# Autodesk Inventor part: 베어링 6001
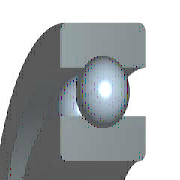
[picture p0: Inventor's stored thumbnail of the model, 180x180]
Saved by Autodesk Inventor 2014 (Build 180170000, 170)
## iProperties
Created: 2012-02
Part Number: 베어링 6001
Material: 강철, 연강
Description: 깊은 그루브 볼 베어링
Document SubType Name: Modeling
Standard: KS B 2023
Designer: mduedu
Standards Organization: KS
Language: ko-KR
Size Designation: 6001 - 12 x 28 x 8
Categories: <MemberInstance><Categories><Category DisplayName="샤프트 부품" InternalName="7f7aeb1f-a693-4053-b835-cee3144e0d98" Mnemonic="SHFT"><Category DisplayName="베어링" Inter
Density: 7.86 g/cm^3
Mass: 21.4855 g
Surface Area: 31.1809 cm^2
Volume: 2.73352 cm^3
Appearance: 노란색
IsCustomPart: 1
Author: mduedu
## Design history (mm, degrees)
sketch "스케치" dims "d0" = 4.16 (= -0.26 x WD + 0.26 x BD)
  geometry: L1 (1.92, 10)-(6.08, 10); L2 (4, 10)-(4, 7.92); L3 (4, 10)-(4, 12.08); L4 (2.454, 8.608)-(0, 8.608); L5 (0, 6)-(8, 6); L6 (2.454, 11.392)-(0, 11.392); L7 (0, 14)-(8, 14); L8 (8, 6)-(8, 8.608); L9 (5.546, 8.608)-(8, 8.608); L10 (5.546, 11.392)-(8, 11.392); L11 (8, 14)-(8, 11.392); L12 (-1.4, 0)-(8.4, 0) reference; L13 (0, -0.3)-(0, 5.3) reference
  constraints: 22 end point, 4 point on line, 2 collinear, 2 perpendicular, 2 symmetric about line, 1 midpoint, 1 parallel, 14 other
  dimensions: "d9" = 12 diameter of L5 L12 (= WD); "d11" = 28 diameter of L7 L12 (= BD); "d12" = 8 distance between parallel lines of L8 L13 (= KB); "d13" = 17.216 diameter of L9 L12 (= 0.326 x BD + 0.674 x WD)
revolve "본체" stored, may be unused: angle "d6" = 90 deg
revolve "볼" stored, may be unused: angle "d7" = 90 deg
pattern_circular "IDS_ARRAYBALL[SIMPL:T]" dims angle "d3" = 360 deg
body "Solid1"
fillet "모깎기1" dims "d1" = 0.3 (= KRS)
other parameters: "WD" = 12 [user parameter; used in 5 equation terms], "BD" = 28 [user parameter; used in 5 equation terms], "KB" = 8 [user parameter; used in 1 equation term], "KRS" = 0.3 [user parameter; used in 1 equation term], "d4" = 0, "d5" = 0, "d8" = 0, "d14" = 0, "d15" = 0, "BBA" = 0 [user parameter], "BC0" = 2360000 [user parameter], "BC" = 5070000 [user parameter], "BR" = 14 (= 0.5 x BD) [user parameter], "WR" = 6 (= 0.5 x WD) [user parameter]
